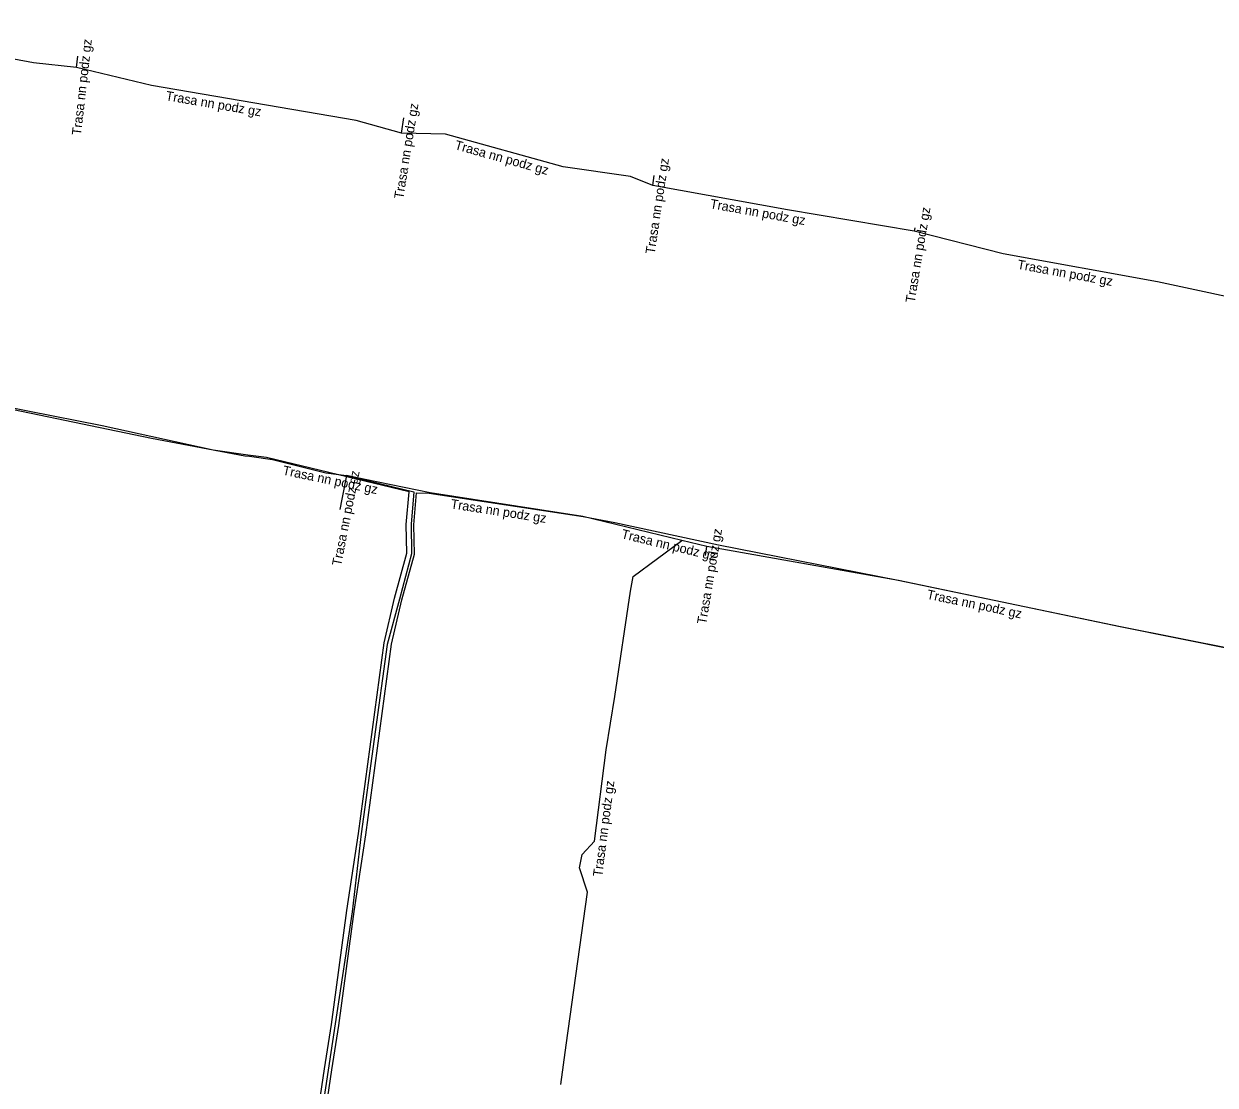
# Model space of a CAD drawing. Extents: x -687924 to -686708, y -1056742 to -1056249.
# Drawn here: x -687225.4 to -687161.7, y -1056512.1 to -1056455.4 of the extents above; entities that cross this region are included whole.
import ezdxf

# ---------------------------------------------------------------- set-up
doc = ezdxf.new("R2010")
doc.units = 0
for name, color, linetype in [('Popiskový text - Ostatní atributy Trasy', 7, 'Continuous'), ('Spojnice NN', 7, 'Continuous'), ('Spojnice VN', 7, 'Continuous')]:
    doc.layers.add(name, color=color, linetype=linetype)

msp = doc.modelspace()

# ---------------------------------------------------------------- linework, layer by layer
at = {"layer": 'Spojnice NN'}
for points in [[(-687222.58, -1056457.71), (-687224.87, -1056457.46), (-687236.06, -1056455.37)], [(-687222.58, -1056457.71), (-687222.51, -1056457.09)], [(-687205.21, -1056461.21), (-687207.64, -1056460.53), (-687218.57, -1056458.66), (-687222.58, -1056457.71)], [(-687205.21, -1056461.21), (-687205.08, -1056460.4)], [(-687191.79, -1056464.01), (-687192.97, -1056463.52), (-687196.58, -1056463.01), (-687202.86, -1056461.26), (-687205.21, -1056461.21)], [(-687191.79, -1056464.01), (-687191.71, -1056463.48)], [(-687177.81, -1056466.44), (-687184.59, -1056465.3), (-687191.79, -1056464.01)], [(-687278.93, -1056465.56), (-687272.69, -1056466.55), (-687271.46, -1056466.75), (-687270.44, -1056466.93), (-687264.59, -1056468.03), (-687255.31, -1056469.93), (-687244.72, -1056472.14), (-687229.23, -1056475.29), (-687218.57, -1056477.5), (-687213.58, -1056478.45), (-687213.33, -1056478.46), (-687212.11, -1056478.65), (-687209.26, -1056479.35), (-687208.15, -1056479.5)], [(-687177.78, -1056466.26), (-687177.81, -1056466.44)], [(-687158.92, -1056470.41), (-687164.82, -1056469.16), (-687173.07, -1056467.66), (-687177.81, -1056466.44)], [(-687208.15, -1056479.5), (-687204.55, -1056480.38), (-687204.7, -1056482.09), (-687204.67, -1056483.68), (-687205.32, -1056486.11), (-687205.97, -1056488.53), (-687207.37, -1056498.65), (-687207.84, -1056502.8), (-687208.76, -1056508.79), (-687213.8, -1056542.15), (-687214.85, -1056549.9)], [(-687208.15, -1056479.5), (-687208.4, -1056480.77), (-687208.5, -1056481.32)], [(-687207.153, -1056479.707), (-687208.15, -1056479.5)], [(-687190.232, -1056482.965), (-687195.52, -1056481.685), (-687203.689, -1056480.424), (-687207.153, -1056479.707)], [(-687196.7, -1056512.04), (-687196.41, -1056509.94), (-687195.27, -1056501.75), (-687195.7, -1056500.46), (-687195.55, -1056499.74), (-687194.9, -1056499.03), (-687194.27, -1056494.16), (-687193.81, -1056491.3), (-687192.97, -1056485.68), (-687192.829, -1056484.893), (-687190.232, -1056482.965)], [(-687188.89, -1056483.29), (-687190.232, -1056482.965)], [(-687188.97, -1056483.765), (-687188.89, -1056483.29)], [(-687157.622, -1056489.464), (-687160.615, -1056488.826), (-687166.818, -1056487.585), (-687178.657, -1056485.1), (-687188.89, -1056483.29)]]:
    msp.add_lwpolyline(points, dxfattribs=at)
at = {"layer": 'Spojnice VN'}
for points in [[(-687205.584, -1056486.046), (-687204.922, -1056483.649), (-687204.957, -1056482.12), (-687204.806, -1056480.373), (-687212.42, -1056478.53), (-687213.43, -1056478.41), (-687215.27, -1056478.14), (-687221.2, -1056476.85), (-687229.16, -1056475.28)], [(-687205.196, -1056486.144), (-687204.52, -1056483.699), (-687204.557, -1056482.132), (-687204.41, -1056480.427), (-687203.73, -1056480.45), (-687195.51, -1056481.69), (-687193.81, -1056482.01), (-687188.28, -1056483.2), (-687178.67, -1056485.09), (-687166.79, -1056487.57), (-687160.61, -1056488.8)], [(-687222.97, -1056605.693), (-687222.668, -1056603.992), (-687221.803, -1056597.925), (-687221.228, -1056594.266), (-687220.668, -1056590.104), (-687219.741, -1056583.022), (-687219.903, -1056581.431), (-687219.245, -1056579.522), (-687218.908, -1056577.301), (-687217.218, -1056565.273), (-687216.448, -1056559.451), (-687215.098, -1056550.89), (-687213.808, -1056541.937), (-687212.448, -1056532.242), (-687209.328, -1056511.189), (-687208.948, -1056508.831), (-687208.138, -1056502.732), (-687207.518, -1056498.632), (-687206.137, -1056488.444), (-687205.584, -1056486.046)], [(-687223.498, -1056611.492), (-687222.813, -1056607.242), (-687222.282, -1056603.92), (-687221.407, -1056597.985), (-687220.832, -1056594.324), (-687220.272, -1056590.156), (-687219.652, -1056585.386), (-687219.339, -1056583.028), (-687219.497, -1056581.479), (-687218.855, -1056579.618), (-687218.512, -1056577.359), (-687216.822, -1056565.327), (-687216.052, -1056559.509), (-687214.702, -1056550.95), (-687213.412, -1056541.993), (-687212.052, -1056532.298), (-687208.932, -1056511.251), (-687208.552, -1056508.889), (-687207.742, -1056502.788), (-687207.122, -1056498.688), (-687205.743, -1056488.516), (-687205.196, -1056486.144)]]:
    msp.add_lwpolyline(points, dxfattribs=at)

# ---------------------------------------------------------------- texts
at = {"layer": 'Popiskový text - Ostatní atributy Trasy'}
for rotation, p in [(83.5584, (-687222.336, -1056461.342)), (350.29134, (-687217.84, -1056459.445)), (80.88214, (-687205.12, -1056464.752)), (344.42884, (-687202.406, -1056462.062)), (81.41638, (-687191.688, -1056467.692)), (349.84228, (-687188.754, -1056465.214)), (80.53768, (-687177.794, -1056470.298)), (349.69515, (-687172.333, -1056468.454)), (348.29257, (-687211.596, -1056479.45)), (78.86369, (-687208.444, -1056484.356)), (351.22485, (-687202.611, -1056481.248)), (346.38645, (-687193.498, -1056482.843)), (80.4399, (-687188.936, -1056487.475)), (348.14433, (-687177.174, -1056486.076)), (82.62896, (-687194.494, -1056500.954))]:
    msp.add_text('Trasa nn podz gz', height=0.5, rotation=rotation, dxfattribs=at).set_placement(p)

doc.saveas('drawing.dxf')
